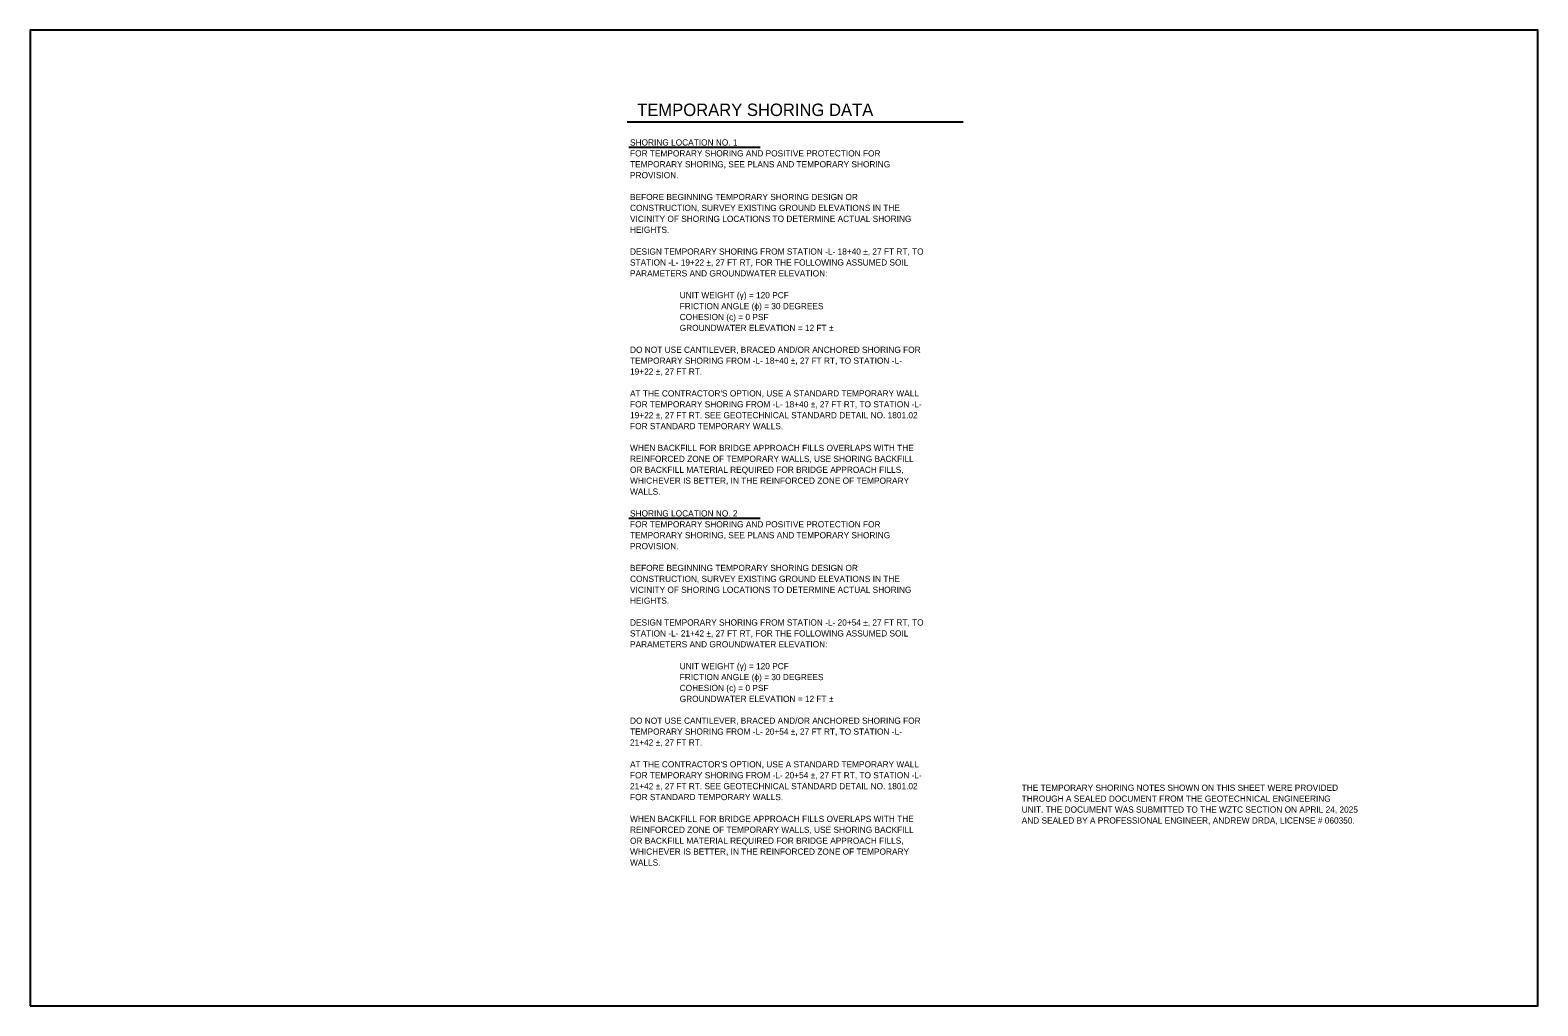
# Model space of a CAD drawing. Extents: x 0 to 1700, y 0 to 1100.
import ezdxf

# ---------------------------------------------------------------- set-up
doc = ezdxf.new("R2010")
doc.units = 0
for name, color, linetype in [('Default', 7, 'Continuous'), ('P_RDY_ROW_Permanent_Easement_CELL', 7, 'Continuous'), ('Sheet_Cross_Section_Scale_CELL', 7, 'Continuous'), ('Sheet_Plan', 7, 'Continuous'), ('Sheet_RDY_XS_Number', 7, 'Continuous')]:
    doc.layers.add(name, color=color, linetype=linetype)

msp = doc.modelspace()

# ---------------------------------------------------------------- linework, layer by layer
at = {"layer": 'Default'}
msp.add_lwpolyline([(0, 0), (1700, 0), (1700, 1100), (0, 1100)], close=True, dxfattribs=at)
at = {"layer": 'P_RDY_ROW_Permanent_Easement_CELL'}
msp.add_line((673.1, 996.7), (1052.2, 996.7), dxfattribs=at)
at = {"layer": 'Sheet_RDY_XS_Number'}
for p, q in [((675.1, 967.9), (823.2, 967.9)), ((675.1, 549.7), (823.2, 549.7))]:
    msp.add_line(p, q, dxfattribs=at)

# ---------------------------------------------------------------- texts
at = {"layer": 'Sheet_Cross_Section_Scale_CELL'}
for s, p in [('SHORING LOCATION NO. 1', (676.4, 969.9)), ('TEMPORARY SHORING, SEE PLANS AND TEMPORARY SHORING ', (676.4, 945.3)), ('FOR TEMPORARY SHORING AND POSITIVE PROTECTION FOR ', (676.4, 957.6)), ('PROVISION.', (676.4, 933)), ('CONSTRUCTION, SURVEY EXISTING GROUND ELEVATIONS IN THE ', (676.4, 896.1)), ('BEFORE BEGINNING TEMPORARY SHORING DESIGN OR ', (676.4, 908.4)), ('VICINITY OF SHORING LOCATIONS TO DETERMINE ACTUAL SHORING ', (676.4, 883.8)), ('HEIGHTS.', (676.4, 871.5)), ('DESIGN TEMPORARY SHORING FROM STATION -L- 18+40 ±, 27 FT RT, TO ', (676.4, 846.9)), ('STATION -L- 19+22 ±, 27 FT RT, FOR THE FOLLOWING ASSUMED SOIL ', (676.4, 834.6)), ('PARAMETERS AND GROUNDWATER ELEVATION:', (676.4, 822.3)), ('UNIT WEIGHT (γ) = 120 PCF', (732.4, 797.7)), ('FRICTION ANGLE (ϕ) = 30 DEGREES', (732.4, 785.4)), ('COHESION (c) = 0 PSF', (732.4, 773.1)), ('GROUNDWATER ELEVATION = 12 FT ±', (732.4, 760.8)), ('TEMPORARY SHORING FROM -L- 18+40 ±, 27 FT RT, TO STATION -L- ', (676.4, 723.9)), ('DO NOT USE CANTILEVER, BRACED AND/OR ANCHORED SHORING FOR ', (676.4, 736.2)), ('19+22 ±, 27 FT RT.', (676.4, 711.6)), ("AT THE CONTRACTOR'S OPTION, USE A STANDARD TEMPORARY WALL ", (676.4, 687)), ('FOR TEMPORARY SHORING FROM -L- 18+40 ±, 27 FT RT, TO STATION -L- ', (676.4, 674.7)), ('19+22 ±, 27 FT RT. SEE GEOTECHNICAL STANDARD DETAIL NO. 1801.02 ', (676.4, 662.4)), ('FOR STANDARD TEMPORARY WALLS.', (676.4, 650.1)), ('WHEN BACKFILL FOR BRIDGE APPROACH FILLS OVERLAPS WITH THE ', (676.4, 625.5)), ('REINFORCED ZONE OF TEMPORARY WALLS, USE SHORING BACKFILL ', (676.4, 613.2)), ('WHICHEVER IS BETTER, IN THE REINFORCED ZONE OF TEMPORARY ', (676.4, 588.6)), ('OR BACKFILL MATERIAL REQUIRED FOR BRIDGE APPROACH FILLS, ', (676.4, 600.9)), ('WALLS.', (676.4, 576.3)), ('SHORING LOCATION NO. 2', (676.4, 551.7)), ('FOR TEMPORARY SHORING AND POSITIVE PROTECTION FOR ', (676.4, 539.4)), ('TEMPORARY SHORING, SEE PLANS AND TEMPORARY SHORING ', (676.4, 527.1)), ('PROVISION.', (676.4, 514.8)), ('BEFORE BEGINNING TEMPORARY SHORING DESIGN OR ', (676.4, 490.2)), ('CONSTRUCTION, SURVEY EXISTING GROUND ELEVATIONS IN THE ', (676.4, 477.9)), ('VICINITY OF SHORING LOCATIONS TO DETERMINE ACTUAL SHORING ', (676.4, 465.6)), ('HEIGHTS.', (676.4, 453.3)), ('DESIGN TEMPORARY SHORING FROM STATION -L- 20+54 ±, 27 FT RT, TO ', (676.4, 428.7)), ('STATION -L- 21+42 ±, 27 FT RT, FOR THE FOLLOWING ASSUMED SOIL ', (676.4, 416.4)), ('PARAMETERS AND GROUNDWATER ELEVATION:', (676.4, 404.1)), ('UNIT WEIGHT (γ) = 120 PCF', (732.4, 379.5)), ('FRICTION ANGLE (ϕ) = 30 DEGREES', (732.4, 367.2)), ('COHESION (c) = 0 PSF', (732.4, 354.9)), ('GROUNDWATER ELEVATION = 12 FT ±', (732.4, 342.6)), ('DO NOT USE CANTILEVER, BRACED AND/OR ANCHORED SHORING FOR ', (676.4, 318)), ('TEMPORARY SHORING FROM -L- 20+54 ±, 27 FT RT, TO STATION -L- ', (676.4, 305.7)), ('21+42 ±, 27 FT RT.', (676.4, 293.4)), ("AT THE CONTRACTOR'S OPTION, USE A STANDARD TEMPORARY WALL ", (676.4, 268.8)), ('FOR TEMPORARY SHORING FROM -L- 20+54 ±, 27 FT RT, TO STATION -L- ', (676.4, 256.5)), ('21+42 ±, 27 FT RT. SEE GEOTECHNICAL STANDARD DETAIL NO. 1801.02 ', (676.4, 244.2)), ('FOR STANDARD TEMPORARY WALLS.', (676.4, 231.9)), ('WHEN BACKFILL FOR BRIDGE APPROACH FILLS OVERLAPS WITH THE ', (676.4, 207.3)), ('OR BACKFILL MATERIAL REQUIRED FOR BRIDGE APPROACH FILLS, ', (676.4, 182.7)), ('REINFORCED ZONE OF TEMPORARY WALLS, USE SHORING BACKFILL ', (676.4, 195)), ('WHICHEVER IS BETTER, IN THE REINFORCED ZONE OF TEMPORARY ', (676.4, 170.4)), ('WALLS.', (676.4, 158.1))]:
    msp.add_text(s, height=7, rotation=360, dxfattribs=at).set_placement(p)
for s, p in [('THE TEMPORARY SHORING NOTES SHOWN ON THIS SHEET WERE PROVIDED ', (1118, 242.4)), ('THROUGH A SEALED DOCUMENT FROM THE GEOTECHNICAL ENGINEERING ', (1118, 230.1)), ('UNIT. THE DOCUMENT WAS SUBMITTED TO THE WZTC SECTION ON APRIL 24, 2025 ', (1118, 217.8)), ('AND SEALED BY A PROFESSIONAL ENGINEER, ANDREW DRDA, LICENSE # 060350.', (1118, 205.5))]:
    msp.add_text(s, height=7, dxfattribs=at).set_placement(p)
at = {"layer": 'Sheet_Plan'}
msp.add_text('TEMPORARY SHORING DATA', height=14, dxfattribs=at).set_placement((684.4, 1003.2))

doc.saveas('drawing.dxf')
